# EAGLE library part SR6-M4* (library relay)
Safety Relay 4 pole 8 A SCHRACK 3 N/O contact and 1 N/C contact Source: http://www.schrack.com/.. 5814.pdf
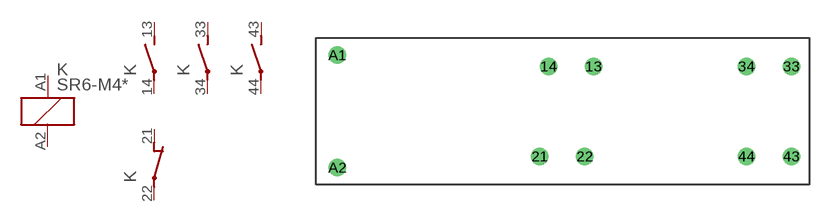
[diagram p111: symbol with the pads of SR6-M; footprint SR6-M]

Designator prefix K; gates 1=K 2=S 3=S 4=S 5=O

## SR6-M4005 (OC_FARNELL: unknown; OC_NEWARK: unknown), SR6-M4006 (OC_FARNELL: unknown; OC_NEWARK: unknown), SR6-M4009 (OC_FARNELL: unknown; OC_NEWARK: unknown), SR6-M4012 (MPN: SR6M4012; OC_FARNELL: 1770624; OC_NEWARK: 51R7442), SR6-M4018 (OC_FARNELL: unknown; OC_NEWARK: unknown), SR6-M4021 (OC_FARNELL: unknown; OC_NEWARK: unknown), SR6-M4024 (MPN: SR6M4024; OC_FARNELL: 1770625; OC_NEWARK: 51R7443), SR6-M4036 (OC_FARNELL: unknown; OC_NEWARK: unknown), SR6-M4040 (OC_FARNELL: unknown; OC_NEWARK: unknown), SR6-M4048 (OC_FARNELL: unknown; OC_NEWARK: unknown), SR6-M4060 (OC_FARNELL: unknown; OC_NEWARK: unknown), SR6-M4085 (OC_FARNELL: unknown; OC_NEWARK: unknown), SR6-M4110 (OC_FARNELL: unknown; OC_NEWARK: unknown)  [SR6-M]
13  2:S  pas
14  2:P  pas
21  5:O  pas
22  5:P  pas
33  3:S  pas
34  3:P  pas
43  4:S  pas
44  4:P  pas
A1  1:1  pas
A2  1:2  pas

## Footprint SR6-M (pad centres in mm)
Safety Relay 4 pole 8 A SCHRACK Configuration 3 N/O contact and 1 N/C contact Source: http://www.schrack.com/.. 5814.pdf
drill 1.3 round: 13 3.5,5; 14 -1.5,5; 21 -2.5,-5; 22 2.5,-5; 33 25.5,5; 34 20.5,5; 43 25.5,-5; 44 20.5,-5; A1 -25,6.25; A2 -25,-6.25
